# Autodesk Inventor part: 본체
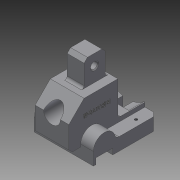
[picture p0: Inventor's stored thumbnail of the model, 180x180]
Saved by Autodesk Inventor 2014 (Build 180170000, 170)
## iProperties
Created: 2016-11
Part Number: 본체
Material: 일반
Document SubType Name: Modeling
Designer: USER
Density: 1 g/cm^3
Appearance: 기본값
Author: USER
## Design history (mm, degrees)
sketch "스케치1"
  geometry: L1 (-27, 12.101)-(-27, 42); L2 (-27, 42)-(-9, 60); L3 (-9, 60)-(1, 60); L4 (1, 60)-(1, 90); L5 (1, 90)-(26, 90); L6 (26, 90)-(26, 60); L7 (26, 60)-(31, 60); L8 (31, 60)-(31, 20); L9 (31, 20)-(63, 20); L10 (63, 20)-(63, 0); L11 (63, 0)-(-13, 0); L12 (-13, 0)-(-13, 12); L13 (-13, 12)-(-27, 12); L14 (-27, 12)-(-27, 12.101); 1 further point
  constraints: 28 end point, 8 parallel, 3 perpendicular, 2 collinear, 1 point on line, 1 vertical
  dimensions: "d0" = 58 distance between parallel lines of L8 L1; "d1" = 90 distance between parallel lines of L10 L1; "d2" = 25 distance of L4.end L5.end; "d3" = 18 distance from line of L2.end L1; "d4" = 5 distance between parallel lines of L8 L6; "d5" = 63 distance from line of point (0, 0) L10; "d6" = 13 distance from line of point (0, 0) L12; "d7" = 90 distance between parallel lines of L5 L11; "d8" = 60 distance between parallel lines of L7 L11; "d9" = 30 distance from line of L1.end L13; "d10" = 45 deg angle of L2 L3; "d11" = 20 distance of L9.end L10.end
extrude "돌출1" new body sketch "스케치1" stored distance "d12" = 70; taper "d13" = 0 deg
sketch "스케치2"
  geometry: L1 (-12, -13)-(0, -13) reference; L2 (0, -13)-(0, 63) reference; L3 (0, -10)-(-7, -10); L4 (-7, -10)-(-7, 10); L5 (-7, 10)-(0, 10); 1 further point
  constraints: 6 end point, 3 perpendicular, 2 point on line
  dimensions: "d14" = 7 distance of L3.start L3.end; "d15" = 20 distance of L3.end L4.end; "d16" = 3 distance between parallel lines of L1 L3
extrude "돌출2" cut sketch "스케치2" stored distance "d17" = 70; taper "d18" = 0 deg
sketch "스케치3"
  geometry: L1 (70, -70)-(0, -70) reference; L2 (70, 0)-(55, 0); L3 (55, 0)-(55, -70); L4 (55, -70)-(70, -70); L5 (70, -70)-(70, 0); L6 (0, 0)-(15, 0); L7 (15, 0)-(15, -70); L8 (15, -70)-(0, -70); L9 (0, -70)-(0, 0); 1 further point
  constraints: 16 end point, 4 parallel, 2 horizontal, 2 perpendicular, 2 point on line, 1 collinear
  dimensions: "d19" = 40 distance between parallel lines of L7 L3
extrude "돌출3" cut sketch "스케치3" stored distance "d20" = 70; taper "d21" = 0 deg
sketch "스케치4"
  geometry: L1 (0, 30)-(0, 0) reference; L2 (40, 0)-(0, 0) reference; L3 (40, 0)-(40, 30) reference; L4 (40, 30)-(0, 30) reference; L5 (30, 0)-(10, 0); L6 (10, 0)-(10, 30); L7 (10, 30)-(30, 30); L8 (30, 30)-(30, 0); L9 (40, 30)-(0, 30) reference; L10 (0, 70)-(0, 30) reference; L11 (40, 30)-(0, 30) reference; L12 (40, 30)-(40, 70) reference; L13 (40, 70)-(0, 70) reference; 3 further points
  constraints: 8 end point, 2 midpoint, 2 parallel, 1 coincident, 1 collinear, 1 horizontal, 1 perpendicular, 1 point on line
  dimensions: "d22" = 20 distance between parallel lines of L6 L8
extrude "돌출4" cut sketch "스케치4" stored distance "d23" = 70; taper "d24" = 0 deg
sketch "스케치5"
  geometry: L1 (-20, -27)-(-42, -27) reference; L2 (-12, -13)-(-20, -13); L3 (-20, -13)-(-20, -27); L4 (-20, -27)-(-12, -27); L5 (-12, -27)-(-12, -13); 1 further point
  constraints: 8 end point, 2 parallel, 1 horizontal, 1 perpendicular
extrude "돌출5" cut sketch "스케치5" stored distance "d25" = 70; taper "d26" = 0 deg
sketch "스케치6"
  geometry: L1 (-20, -13)-(0, -13) reference; L2 (-7, -10)-(-7, 10) reference; L3 (-7, 10)-(0, 10) reference; L4 (0, 10)-(0, 63) reference; L5 (-20, 63)-(-20, -13) reference; L6 (-20, -12)-(-20, -13); A1 r 13 centre (-15, 0) between (-20, -12) and (-15, -13); A2 r 13 centre (-15, 0) between (-6.693, 10) and (-7, 10.247); 1 further point
  constraints: 4 point on circle, 4 point on line, 2 centre point, 2 end point, 1 collinear, 1 horizontal alignment
  dimensions: "d28" = 15 distance from line of L4 A1.centre; "d29" = 1 distance of L1.start L6.start
extrude "돌출6" cut sketch "스케치6" stored distance "d30" = 70; taper "d31" = 0 deg
sketch "스케치7"
  geometry: L1 (0, 10)-(0, 63) reference; C1 r 13 at (-15, 0); 1 further point
  constraints: 1 centre point, 1 horizontal alignment
  dimensions: "d32" = 26 diameter of C1; "d33" = 15 distance from line of L1 C1.centre
extrude "돌출7" join sketch "스케치7" stored distance "d34" = 70; taper "d35" = 0 deg
sketch "스케치8"
  geometry: L1 (0, -10)-(-7, -10); L2 (-7, -10)-(-7, 10); L3 (-7, 10)-(0, 10); L4 (0, 10)-(0, -10); 1 further point
  constraints: 8 end point, 2 parallel, 1 horizontal, 1 perpendicular
  dimensions: "d36" = 20 distance of L3.end L1.start; "d37" = 7 distance of L2.end L3.end
extrude "돌출8" cut sketch "스케치8" stored distance "d38" = 70; taper "d39" = 0 deg
sketch "스케치9"
  geometry: L1 (-7, 10)-(0, 10) reference; L2 (0, 10)-(0, 63) reference; L3 (0, 63)-(-20, 63) reference; L4 (-20, 63)-(-20, 12) reference; L5 (-15, -13)-(0, -13) reference; L6 (0, -13)-(0, -10) reference; L7 (0, -10)-(-7, -10) reference; L8 (-7, -10)-(-7, 10) reference; L9 (0, -13)-(-45.317, -13); L10 (-45.317, -13)-(-45.317, 63); L11 (-45.317, 63)-(0, 63); L12 (0, 63)-(0, -13); A1 r 13 centre (-15, 0) between (-20, 12) and (-15, -13) reference; 1 further point
  constraints: 8 end point, 2 parallel, 1 collinear, 1 horizontal, 1 perpendicular
  dimensions: "d40" = 45.31713 distance between parallel lines of L2 L10
extrude "돌출9" join sketch "스케치9" stored distance "d41" = 70; taper "d42" = 0 deg
sketch "스케치10"
  geometry: L1 (0, -13)-(0, 63) reference; L2 (0, 63)-(-45.317, 63) reference; L3 (-45.317, 63)-(-45.317, -13) reference; L4 (-45.317, -13)-(0, -13) reference; L5 (-15, 63)-(-15, 17.292); L6 (-15, -13)-(0, -13); L7 (0, -10)-(-7, -10); L8 (-7, -10)-(-7, 10); L9 (-7, 10)-(0, 10); L10 (0, 63)-(-15, 63); A1 r 5 centre (-20, 17.292) between (-18.611, 12.488) and (-15, 17.292); A2 r 13 centre (-15, 0) between (-18.611, 12.488) and (-15, -13); 1 further point
  constraints: 12 end point, 4 perpendicular, 4 point on circle, 4 point on line, 3 tangent, 2 centre point, 2 collinear, 1 parallel, 1 vertical alignment
  dimensions: "d43" = 13 radius of A2; "d44" = 5 radius of A1; "d45" = 15 distance between parallel lines of L1 L5; "d46" = 3 distance between parallel lines of L4 L7; "d47" = 20 distance between parallel lines of L9 L7; "d48" = 7 distance between parallel lines of L1 L8
extrude "돌출10" cut sketch "스케치10" stored distance "d49" = 70; taper "d50" = 0 deg
sketch "스케치11"
  geometry: L1 (30, -25)-(0, -25) reference; L2 (0, -25)-(0, 0) reference; 2 further points
  dimensions: "d51" = 12.5 distance from line of L1 point (13, -12.5); "d52" = 13 distance from line of point (13, -12.5) L2
hole "구멍1" sketch "스케치11" at (13, -12.5) diameter "d53" = 8; stored, may be unused: countersink angle "d57" = 90 deg, drill point angle "d59" = 118 deg; dims "d54" = 6, "d55" = 4, "d56" = 2, "d58" = 8
chamfer "모따기1" distance "d60" = 1; stored, may be unused: second distance "d61" = 2, angle "d62" = 45 deg
sketch "스케치12"
  geometry: L1 (55, 60)-(-15, 60) reference; 3 further points
  constraints: 1 midpoint, 1 vertical alignment
  dimensions: "d63" = 42 distance from line of L1 point (20, 18)
hole "구멍2" sketch "스케치12" at (20, 18) diameter "d64" = 20; stored, may be unused: countersink angle "d68" = 90 deg, drill point angle "d70" = 118 deg; dims "d65" = 6, "d66" = 29, "d67" = 7, "d69" = 8
chamfer "모따기2" distance "d71" = 1; stored, may be unused: second distance "d72" = 2, angle "d73" = 45 deg
sketch "스케치13"
  geometry: L1 (55, -20)-(15, -20) reference; L2 (70, 0)-(0, 0) reference; L3 (41, 0)-(29, 0); L4 (29, 0)-(29, -20); L5 (29, -20)-(41, -20); L6 (41, -20)-(41, 0); C1 r 11 at (35, -42) reference; A1 r 29 centre (35, -42) between (53.894, -20) and (16.106, -20); 3 further points
  constraints: 8 end point, 3 point on line, 2 midpoint, 2 parallel, 2 point on circle, 1 centre point, 1 coincident, 1 collinear, 1 horizontal, 1 perpendicular, 1 vertical alignment
  dimensions: "d74" = 58 diameter of A1; "d75" = 12 distance of L4.end L5.end
extrude "돌출11" cut sketch "스케치13" distance "d76" = 18; taper "d77" = 0 deg
sketch "스케치14"
  geometry: L1 (0, 45.708)-(0, 0) reference; L2 (-15, 45.708)-(0, 45.708) reference; 2 further points
  dimensions: "d78" = 18 distance from line of L2 point (-7.5, 27.708); "d79" = 7.5 distance from line of L1 point (-7.5, 27.708)
hole "구멍3" sketch "스케치14" at (-7.5, 27.708) diameter "d80" = 3.242; stored, may be unused: countersink angle "d84" = 90 deg, drill point angle "d86" = 118 deg; dims "d81" = 6, "d82" = 29, "d83" = 7, "d85" = 8
fillet "모깎기1" dims "d87" = 3
chamfer "모따기3" distance "d88" = 4; stored, may be unused: second distance "d89" = 2, angle "d90" = 45 deg
fillet "모깎기2" dims "d91" = 3
chamfer "모따기4" distance "d92" = 5; stored, may be unused: second distance "d93" = 2, angle "d94" = 45 deg
node "작업 평면1"
sketch "스케치15"
  geometry: L1 (31, 60)-(31, 23) reference; L2 (-9, 60)-(31, 60) reference; 2 further points
  constraints: 1 other
  dimensions: "d96" = 25 distance from line of L1 point (6, 42); "d97" = 18 distance from line of L2 point (6, 42)
feature "엠보싱1" sketch "스케치15" dims "d98" = 0.5, "d99" = 0
node "솔리드1"
mirror "대칭1"
mirror "대칭2"
mirror "대칭3"
mirror "대칭4"
mirror "대칭5"
node "투영된 루프1"
other parameters: "d27" = 26, "d95" = 77.25
